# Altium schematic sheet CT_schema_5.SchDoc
size 258 x 163 mm
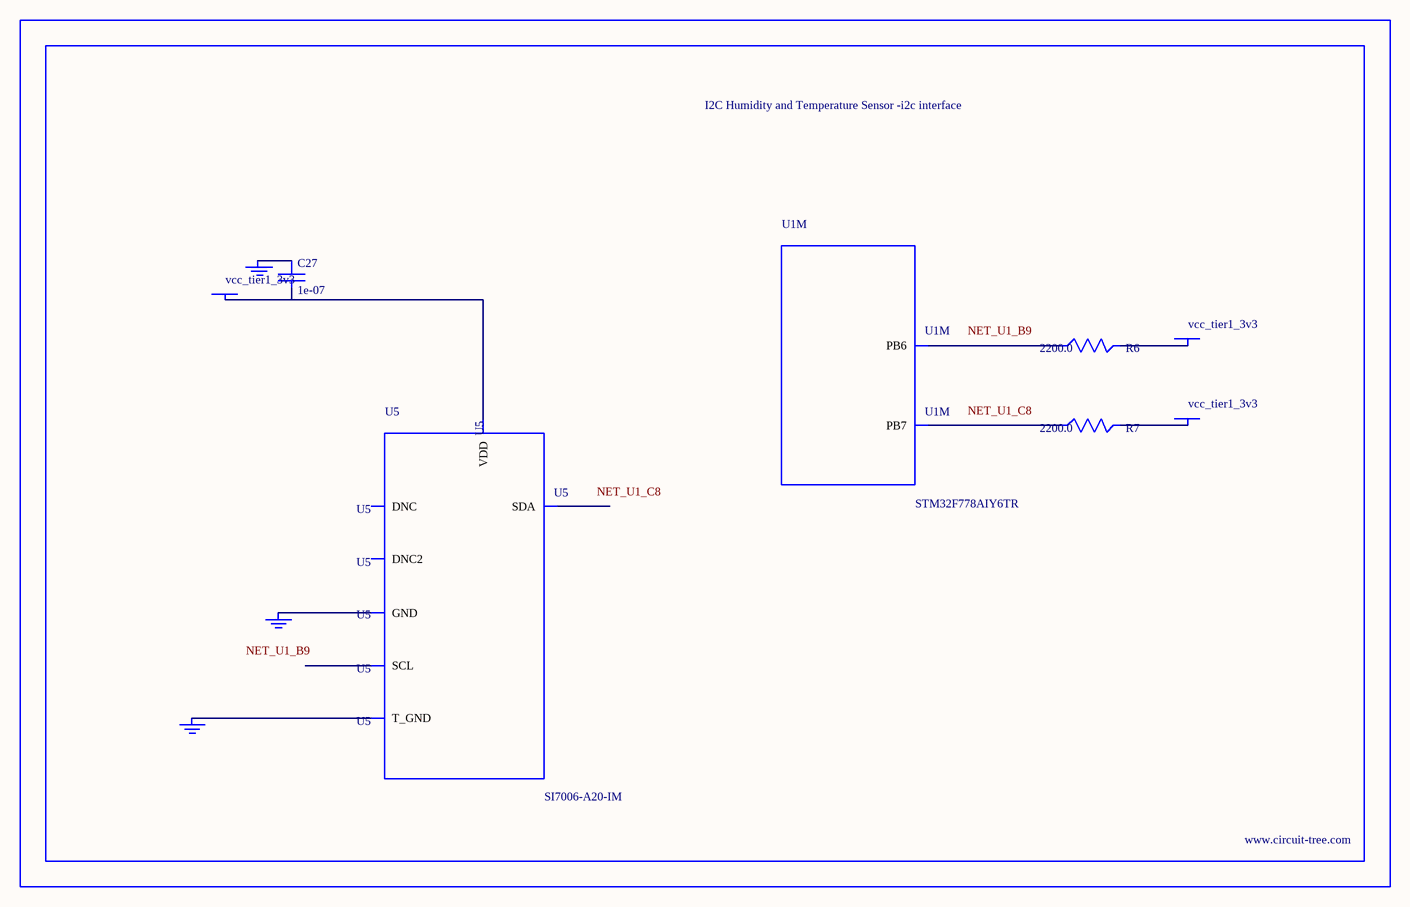
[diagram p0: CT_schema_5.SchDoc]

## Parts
BORDER4  (no value)
C27  1e-07  [C0402]
GND_INSTANCE_4_0  (no value)
GND_INSTANCE_4_1  (no value)
GND_INSTANCE_4_2  (no value)
POWER_INSTANCE_4_0  vcc_tier1_3v3
POWER_INSTANCE_4_1  vcc_tier1_3v3
POWER_INSTANCE_4_2  vcc_tier1_3v3
R6  2200.0  [R0603]
R7  2200.0  [R0603]
U1  STM32F778AIY6TR  [WLCSP180]  (part M of 15)
U5  SI7006-A20-IM  [DFN-6]

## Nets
NetC27_1: C27.1 GND_INSTANCE_4_0.0(GND)
NetC27_2: C27.2 POWER_INSTANCE_4_0.0(PWR) U5.5(VDD)
NetGND_INSTANCE_4_1_0: GND_INSTANCE_4_1.0(GND) U5.7(T_GND)
NetGND_INSTANCE_4_2_0: GND_INSTANCE_4_2.0(GND) U5.2(GND)
NetPOWER_INSTANCE_4_1_0: POWER_INSTANCE_4_1.0(PWR) R6.2
NetPOWER_INSTANCE_4_2_0: POWER_INSTANCE_4_2.0(PWR) R7.2
NetR6_1: R6.1 U1.B9(PB6)
NetR7_1: R7.1 U1.C8(PB7)

Not connected (* = marked no-connect by the designer): U5 1(SDA) 3(DNC) 4(DNC2) 6(SCL)

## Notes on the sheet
- Labels drawn without touching a wire or pin: NET_U1_B9, NET_U1_C8

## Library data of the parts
BORDER4 = BORDER_PAGE4
C27 = C0402C104K3RACTU
GND_INSTANCE_4_0-GND_INSTANCE_4_2 = GND
POWER_INSTANCE_4_0-POWER_INSTANCE_4_2 = PWR
R6 R7 = RC0603JR-072K2L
